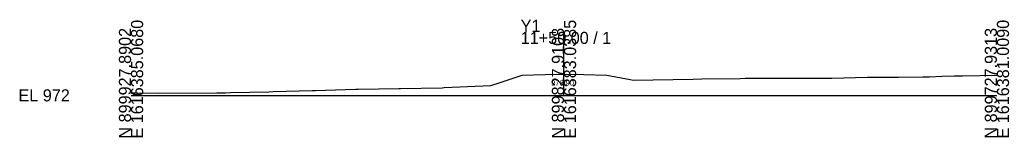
# Model space of a CAD drawing. Extents: x -26 to 203, y -10 to 2022.
# Drawn here: x -25.7 to 202.8, y 1490.3 to 1517.5 of the extents above; entities that cross this region are included whole.
import ezdxf

# ---------------------------------------------------------------- set-up
doc = ezdxf.new("R2010")
doc.units = 0
for name, color, linetype in [('Exist Cross Section Cell', 7, 'Continuous'), ('Exist XS Center Line Elevation Label', 7, 'Continuous'), ('Exist XS Ground Line', 7, 'Continuous')]:
    doc.layers.add(name, color=color, linetype=linetype)

msp = doc.modelspace()

# ---------------------------------------------------------------- linework, layer by layer
at = {"layer": 'Exist Cross Section Cell'}
for p, q in [((100, 1500), (100, 1514.7)), ((0, 1500), (100, 1500)), ((100, 1500), (200, 1500))]:
    msp.add_line(p, q, dxfattribs=at)
at = {"layer": 'Exist XS Ground Line'}
for p, q in [((85.3, 1502.95), (90.38, 1504.66)), ((90.38, 1504.66), (95.63, 1504.79)), ((95.63, 1504.79), (100.03, 1504.9)), ((100.03, 1504.9), (104.6, 1504.82)), ((104.6, 1504.82), (109.93, 1504.69)), ((109.93, 1504.69), (115.28, 1503.67)), ((115.98, 1503.54), (129.86, 1503.77)), ((129.86, 1503.77), (131.86, 1503.81)), ((131.86, 1503.81), (140.67, 1503.92)), ((140.67, 1503.92), (141.86, 1503.95)), ((141.86, 1503.95), (150.47, 1503.98)), ((150.47, 1503.98), (151.86, 1503.96)), ((151.86, 1503.96), (160.28, 1503.97)), ((160.28, 1503.97), (161.86, 1503.99)), ((161.86, 1503.99), (170.08, 1504.21)), ((170.08, 1504.21), (171.86, 1504.24)), ((171.86, 1504.24), (177.27, 1504.24)), ((177.27, 1504.24), (182.9, 1504.25)), ((182.9, 1504.25), (184.46, 1504.32)), ((184.46, 1504.32), (187.28, 1504.42)), ((187.28, 1504.42), (190.13, 1504.49)), ((190.13, 1504.49), (192.08, 1504.52)), ((192.08, 1504.52), (200, 1504.67)), ((52.44, 1501.45), (61.84, 1501.56)), ((61.84, 1501.56), (62.24, 1501.56)), ((62.24, 1501.56), (71.84, 1501.78)), ((71.84, 1501.78), (72.29, 1501.8)), ((72.29, 1501.8), (83.13, 1502.3)), ((83.13, 1502.3), (85.3, 1502.95)), ((115.28, 1503.67), (115.98, 1503.54)), ((0, 1500.6), (0.53, 1500.62)), ((0.53, 1500.62), (1.01, 1500.62)), ((1.01, 1500.62), (1.58, 1500.6)), ((1.58, 1500.6), (6.42, 1500.5)), ((6.42, 1500.5), (19.85, 1500.59)), ((19.85, 1500.59), (21.83, 1500.61)), ((21.83, 1500.61), (23.03, 1500.64)), ((23.03, 1500.64), (31.83, 1500.83)), ((31.83, 1500.83), (32.83, 1500.86)), ((32.83, 1500.86), (41.83, 1501.12)), ((41.83, 1501.12), (42.64, 1501.15)), ((42.64, 1501.15), (51.83, 1501.44)), ((51.83, 1501.44), (52.44, 1501.45))]:
    msp.add_line(p, q, dxfattribs=at)

# ---------------------------------------------------------------- texts
at = {"layer": 'Exist Cross Section Cell'}
for s, p in [('Y1', (90, 1514.7)), ('11+50.00 / 1', (90, 1511.9)), ('EL 972', (-26, 1498.6))]:
    msp.add_text(s, height=2.8, dxfattribs=at).set_placement(p)
for s, p in [('N 899927.8902', (0, 1490)), ('E 1616385.0680', (2.8, 1490)), ('N 899827.9108', (100, 1490)), ('E 1616383.0385', (102.8, 1490)), ('N 899727.9313', (200, 1490)), ('E 1616381.0090', (202.8, 1490))]:
    msp.add_text(s, height=2.8, rotation=90, dxfattribs=at).set_placement(p)
at = {"layer": 'Exist XS Center Line Elevation Label'}
msp.add_text('976.90', height=1.25, dxfattribs=at).set_placement((97.02, 1502.27))

doc.saveas('drawing.dxf')
